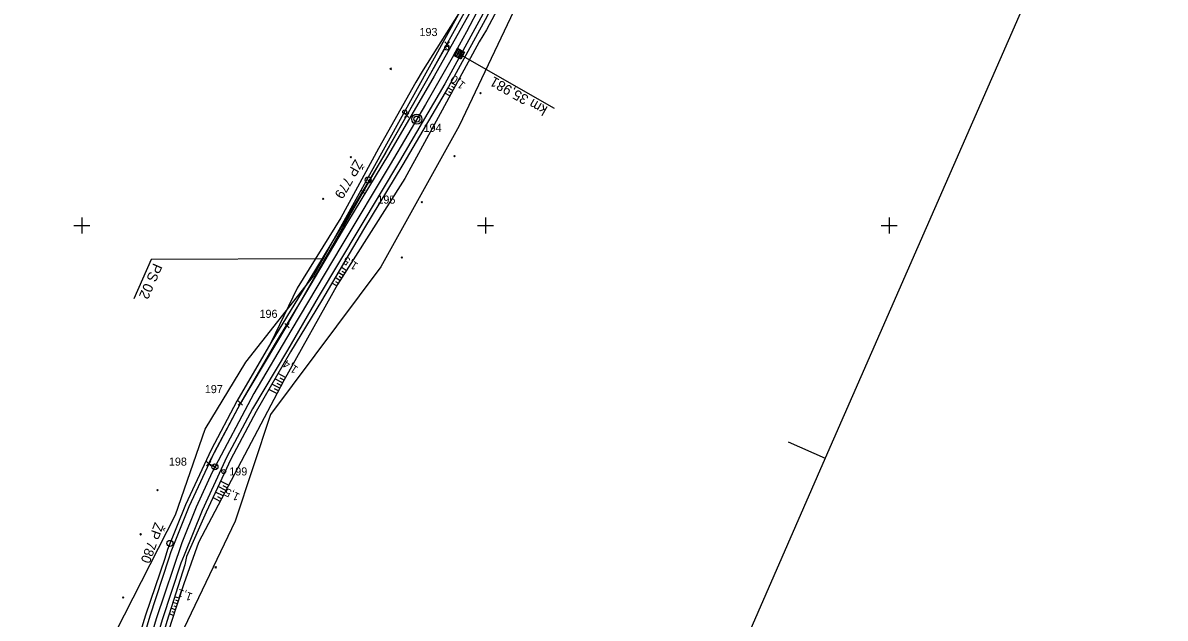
# Model space of a CAD drawing. Extents: x -806856 to -806332, y -1151642 to -1150946.
# Drawn here: x -806614.6 to -806331.6, y -1151297.3 to -1151149.8 of the extents above; entities that cross this region are included whole.
import ezdxf

# ---------------------------------------------------------------- set-up
doc = ezdxf.new("R2010")
doc.units = 0
for name, color, linetype in [('0381KM032-037P - Vrstva 1', 7, 'Continuous'), ('0381KM032-037P - Vrstva 27', 7, 'Continuous'), ('0381KM032-037P - Vrstva 3', 7, 'Continuous'), ('0381KM032-037P - Vrstva 4', 7, 'Continuous'), ('0381KM032-037P - Vrstva 48', 7, 'Continuous'), ('0381KM032-037P - Vrstva 49', 7, 'Continuous'), ('0381KM032-037P - Vrstva 7', 7, 'Continuous'), ('Default', 7, 'Continuous'), ('formát', 7, 'Continuous'), ('hran DP - hran DP', 7, 'Continuous'), ('krizky_1000 - Vrstva 1', 7, 'Continuous'), ('PSR_C2_2_Lomove_body_Vimperk - Vrstva 60', 7, 'Continuous'), ('PSR_C2_2_trasa_Vimperk - Kabelová trasa', 7, 'Continuous'), ('SOPS', 7, 'Continuous'), ('vyt_sit - ohrožené', 7, 'Continuous'), ('vyt_sit - stávající', 7, 'Continuous')]:
    doc.layers.add(name, color=color, linetype=linetype)

msp = doc.modelspace()

# ---------------------------------------------------------------- linework, layer by layer
at = {"layer": '0381KM032-037P - Vrstva 1'}
for points in [[(-806459.11, -1151042.15), (-806463.27, -1151055.58), (-806467.76, -1151068.75), (-806472.65, -1151081.99), (-806477.96, -1151095.43), (-806483.66, -1151108.91), (-806489.46, -1151121.74), (-806491.74, -1151126.53), (-806497.91, -1151139.08), (-806504.69, -1151152.02), (-806507.41, -1151157), (-806508.24, -1151158.47)], [(-806508.24, -1151158.47), (-806514.85, -1151170.04), (-806523.65, -1151184.88)], [(-806523.65, -1151184.88), (-806535.6, -1151204.92), (-806548.25, -1151226.13)], [(-806548.25, -1151226.13), (-806557.37, -1151241.69), (-806567.71, -1151261.13)], [(-806567.71, -1151261.13), (-806571.7, -1151269.85), (-806575.25, -1151278.64)], [(-806575.26, -1151278.66), (-806581.61, -1151297.45), (-806587.32, -1151317.2)]]:
    msp.add_lwpolyline(points, dxfattribs=at)
at = {"layer": '0381KM032-037P - Vrstva 27'}
msp.add_line((-806509.65, -1151156.05), (-806509.55, -1151156.05), dxfattribs=at)
msp.add_circle((-806509.6, -1151156.05), 0.5, dxfattribs=at)
at = {"layer": '0381KM032-037P - Vrstva 3'}
for p, q in [((-806507.53, -1151158.07), (-806507.7, -1151157.51)), ((-806507.07, -1151158.32), (-806507.44, -1151157.05)), ((-806507.41, -1151157), (-806483.02, -1151170.91)), ((-806506.6, -1151158.58), (-806507.19, -1151156.58)), ((-806506.14, -1151158.83), (-806506.93, -1151156.12)), ((-806505.88, -1151158.37), (-806506.47, -1151156.37)), ((-806505.63, -1151157.9), (-806506, -1151156.63)), ((-806505.37, -1151157.44), (-806505.54, -1151156.88))]:
    msp.add_line(p, q, dxfattribs=at)
msp.add_lwpolyline([(-806507.89, -1151157.87), (-806506.93, -1151156.12), (-806505.18, -1151157.08), (-806506.14, -1151158.83)], close=True, dxfattribs=at)
at = {"layer": '0381KM032-037P - Vrstva 4'}
for points in [[(-806449.56, -1151013.68), (-806449.62, -1151013.88), (-806452.81, -1151025.46), (-806457.3, -1151041.13), (-806462.78, -1151058.55), (-806470.34, -1151080.36), (-806477.94, -1151099.38), (-806485.55, -1151116.61), (-806493.04, -1151132.58), (-806500.67, -1151147.66), (-806510.08, -1151164.94), (-806521.27, -1151184.09), (-806531.11, -1151200.55)], [(-806448.21, -1151014.27), (-806448.22, -1151014.33), (-806451.54, -1151025.93), (-806456.14, -1151041.58), (-806461.64, -1151059.21), (-806469.17, -1151081.08), (-806476.72, -1151099.82), (-806484.37, -1151117.46), (-806491.94, -1151132.93), (-806500.08, -1151149.04), (-806509.16, -1151165.69), (-806520.46, -1151184.9), (-806530.22, -1151201.05)], [(-806453.41, -1151012), (-806457.09, -1151024.8), (-806461.35, -1151040.24), (-806466.6, -1151057.45), (-806474.53, -1151080.31), (-806481.65, -1151097.72), (-806488.93, -1151114.87), (-806496.54, -1151130.59), (-806504.49, -1151145.86), (-806513.59, -1151162.34)], [(-806452.41, -1151012.43), (-806452.61, -1151013.14), (-806455.7, -1151025.15), (-806460.24, -1151040.55), (-806465.79, -1151057.73), (-806473.74, -1151080.66), (-806480.83, -1151098.02), (-806488.21, -1151115.16), (-806495.76, -1151130.97), (-806503.39, -1151146.39), (-806512.71, -1151163.05)], [(-806513.59, -1151162.34), (-806524.74, -1151181.99), (-806534.73, -1151198.81)], [(-806512.71, -1151163.05), (-806524.03, -1151182.45), (-806534.14, -1151199.19)], [(-806534.73, -1151198.81), (-806545.37, -1151216.39), (-806553.18, -1151229.13), (-806561.58, -1151243.53), (-806567.96, -1151255.6), (-806574.3, -1151269.24), (-806578.76, -1151280.27), (-806579.4, -1151282.54), (-806584.22, -1151296.56), (-806589.48, -1151313.82), (-806594.95, -1151333.92), (-806600.1, -1151352.67), (-806608.81, -1151384.22), (-806613.08, -1151400.58)], [(-806534.14, -1151199.19), (-806544.55, -1151216.75), (-806552.31, -1151229.7), (-806560.71, -1151244.03), (-806567.24, -1151256.24), (-806573.52, -1151269.73), (-806577.97, -1151280.92), (-806578.5, -1151282.67), (-806583.15, -1151296.86), (-806588.26, -1151314.07), (-806594.08, -1151334.22), (-806599.38, -1151352.89), (-806608.02, -1151384.26), (-806612.6, -1151400.79)], [(-806531.11, -1151200.55), (-806541.48, -1151217.8), (-806549.08, -1151230.92), (-806557.69, -1151245.47), (-806564.05, -1151257.36), (-806570.21, -1151270.63), (-806574.62, -1151281.75), (-806575.45, -1151283.67), (-806580.1, -1151297.77), (-806585.12, -1151314.97), (-806590.56, -1151334.63), (-806595.8, -1151353.37), (-806604.61, -1151384.9), (-806609.41, -1151402.19)], [(-806530.22, -1151201.05), (-806540.66, -1151218.65), (-806548.31, -1151231.35), (-806556.78, -1151246.08), (-806563.07, -1151257.89), (-806569.22, -1151271.02), (-806574.1, -1151282.08), (-806574.48, -1151284.1), (-806578.97, -1151298.16), (-806583.83, -1151315.38), (-806589.34, -1151334.88), (-806594.45, -1151353.63), (-806603.42, -1151385.04), (-806608.69, -1151402.5)]]:
    msp.add_lwpolyline(points, dxfattribs=at)
at = {"layer": '0381KM032-037P - Vrstva 48'}
for p, q in [((-806508.1, -1151166.54), (-806509.29, -1151165.9)), ((-806508.45, -1151167.2), (-806509.06, -1151166.88)), ((-806507.39, -1151165.22), (-806508.56, -1151164.59)), ((-806507.74, -1151165.88), (-806508.33, -1151165.56)), ((-806508.81, -1151167.86), (-806510.05, -1151167.2)), ((-806535.27, -1151212.43), (-806536.5, -1151211.65)), ((-806534.47, -1151211.16), (-806535.73, -1151210.35)), ((-806534.87, -1151211.79), (-806535.49, -1151211.4)), ((-806536.85, -1151214.97), (-806538.08, -1151214.31)), ((-806536.08, -1151213.69), (-806537.27, -1151212.94)), ((-806536.48, -1151214.33), (-806537.06, -1151213.95)), ((-806535.67, -1151213.06), (-806536.28, -1151212.68)), ((-806549.55, -1151237.71), (-806551.38, -1151236.68)), ((-806549.91, -1151238.36), (-806550.83, -1151237.85)), ((-806551.66, -1151241.68), (-806553.65, -1151240.63)), ((-806550.96, -1151240.35), (-806552.9, -1151239.33)), ((-806551.31, -1151241.01), (-806552.29, -1151240.5)), ((-806550.26, -1151239.02), (-806552.15, -1151238.03)), ((-806550.61, -1151239.69), (-806551.57, -1151239.18)), ((-806563.63, -1151264.4), (-806565.62, -1151263.35)), ((-806565.02, -1151267.05), (-806566.9, -1151266.07)), ((-806564.33, -1151265.73), (-806566.26, -1151264.71)), ((-806564.67, -1151266.39), (-806565.63, -1151265.89)), ((-806563.97, -1151265.06), (-806564.96, -1151264.54)), ((-806565.72, -1151268.38), (-806567.54, -1151267.43)), ((-806565.37, -1151267.72), (-806566.3, -1151267.23)), ((-806576.33, -1151293.8), (-806577.46, -1151293.43)), ((-806576.56, -1151294.51), (-806577.15, -1151294.32)), ((-806575.86, -1151292.37), (-806577, -1151292)), ((-806576.1, -1151293.08), (-806576.71, -1151292.89)), ((-806577.26, -1151296.65), (-806578.37, -1151296.29)), ((-806576.79, -1151295.22), (-806577.92, -1151294.86)), ((-806577.02, -1151295.94), (-806577.6, -1151295.75))]:
    msp.add_line(p, q, dxfattribs=at)
at = {"layer": '0381KM032-037P - Vrstva 49'}
for p, q in [((-806523.3, -1151161.03), (-806523.66, -1151161.38)), ((-806523.66, -1151161.03), (-806523.3, -1151161.38)), ((-806501.03, -1151167.07), (-806501.39, -1151167.43)), ((-806501.39, -1151167.08), (-806501.03, -1151167.43)), ((-806533.51, -1151182.94), (-806533.15, -1151183.29)), ((-806533.15, -1151182.94), (-806533.5, -1151183.29)), ((-806507.48, -1151182.67), (-806507.84, -1151183.02)), ((-806507.84, -1151182.67), (-806507.48, -1151183.02)), ((-806540.04, -1151193.21), (-806540.39, -1151193.57)), ((-806540.39, -1151193.21), (-806540.03, -1151193.57)), ((-806515.61, -1151194.06), (-806515.96, -1151194.41)), ((-806515.96, -1151194.06), (-806515.61, -1151194.41)), ((-806520.55, -1151207.75), (-806520.9, -1151208.11)), ((-806520.9, -1151207.76), (-806520.54, -1151208.11)), ((-806581.43, -1151265.45), (-806581.07, -1151265.8)), ((-806581.07, -1151265.45), (-806581.42, -1151265.81)), ((-806585.29, -1151276.36), (-806585.64, -1151276.72)), ((-806585.64, -1151276.36), (-806585.29, -1151276.72)), ((-806566.67, -1151284.56), (-806567.02, -1151284.92)), ((-806567.02, -1151284.56), (-806566.66, -1151284.92)), ((-806589.55, -1151292.05), (-806589.91, -1151292.41)), ((-806589.91, -1151292.05), (-806589.55, -1151292.41))]:
    msp.add_line(p, q, dxfattribs=at)
for points in [[(-806448.2, -1151014.28), (-806448.22, -1151014.33), (-806451.54, -1151025.93), (-806456.14, -1151041.58), (-806461.64, -1151059.21), (-806469.17, -1151081.08), (-806476.72, -1151099.82), (-806484.37, -1151117.46), (-806491.94, -1151132.93), (-806500.08, -1151149.04), (-806509.16, -1151165.69), (-806520.46, -1151184.9), (-806530.22, -1151201.05)], [(-806446.83, -1151014.88), (-806447.16, -1151016), (-806450, -1151026.43), (-806453.97, -1151042.26), (-806459.11, -1151060.35), (-806468.36, -1151084.26), (-806475.1, -1151100.8), (-806483.46, -1151117.96), (-806490.37, -1151133.75), (-806499.76, -1151151.57), (-806501.59, -1151154.48), (-806510.73, -1151171.42), (-806520.01, -1151188.39)], [(-806496.54, -1151130.59), (-806505.32, -1151145.34), (-806515.42, -1151161.45), (-806517.29, -1151164.53), (-806526.47, -1151180.94), (-806535.85, -1151198.12)], [(-806520.01, -1151188.39), (-806536.66, -1151214.61), (-806549.93, -1151238.4), (-806571.09, -1151278.57), (-806574.7, -1151288.79), (-806577.92, -1151298.67), (-806582.99, -1151315.77), (-806588.39, -1151335.12), (-806593.7, -1151353.88), (-806600.16, -1151386.57)], [(-806535.85, -1151198.12), (-806546.61, -1151215.57), (-806553.18, -1151229.13), (-806561.58, -1151243.53), (-806567.96, -1151255.6), (-806574.3, -1151269.24), (-806578.76, -1151280.27), (-806579.4, -1151282.54), (-806584.22, -1151296.56), (-806589.48, -1151313.82), (-806594.95, -1151333.92), (-806600.1, -1151352.67), (-806608.81, -1151384.22), (-806614.6, -1151399.91)], [(-806530.22, -1151201.05), (-806540.66, -1151218.65), (-806548.31, -1151231.35), (-806556.78, -1151246.08), (-806563.07, -1151257.89), (-806569.22, -1151271.02), (-806574.1, -1151282.08)], [(-806574.1, -1151282.08), (-806574.48, -1151284.1), (-806578.97, -1151298.16), (-806583.83, -1151315.38), (-806589.34, -1151334.88), (-806594.45, -1151353.63), (-806603.42, -1151385.04), (-806608.48, -1151402.59)]]:
    msp.add_lwpolyline(points, dxfattribs=at)
at = {"layer": '0381KM032-037P - Vrstva 7'}
for p, q in [((-806520.04, -1151171.89), (-806519.94, -1151171.89)), ((-806564.89, -1151260.99), (-806564.79, -1151260.99))]:
    msp.add_line(p, q, dxfattribs=at)
for centre, radius in [((-806519.99, -1151171.89), 0.5), ((-806517, -1151173.66), 1.25), ((-806517, -1151173.66), 0.752), ((-806567.02, -1151259.83), 0.75), ((-806564.84, -1151260.99), 0.5)]:
    msp.add_circle(centre, radius, dxfattribs=at)
at = {"layer": 'formát'}
for p, q in [((-806331.63, -1151065.3), (-806415.83, -1151257.68)), ((-806424.99, -1151253.67), (-806415.83, -1151257.68)), ((-806424.99, -1151253.67), (-806415.83, -1151257.68)), ((-806415.83, -1151257.68), (-806500.03, -1151450.06))]:
    msp.add_line(p, q, dxfattribs=at)
at = {"layer": 'hran DP - hran DP'}
for p, q in [((-806485.36, -1151130.76), (-806506.53, -1151175.36)), ((-806542.64, -1151212.58), (-806506.25, -1151146.99)), ((-806506.53, -1151175.36), (-806525.91, -1151210.3)), ((-806525.91, -1151210.3), (-806553.28, -1151246.87)), ((-806559.38, -1151233.91), (-806542.64, -1151212.58)), ((-806569.42, -1151250.48), (-806559.38, -1151233.91)), ((-806553.28, -1151246.87), (-806561.98, -1151273.31)), ((-806576.79, -1151271.69), (-806569.42, -1151250.48)), ((-806591.51, -1151300.57), (-806576.79, -1151271.69)), ((-806561.98, -1151273.31), (-806579.39, -1151309.52))]:
    msp.add_line(p, q, dxfattribs=at)
at = {"layer": 'krizky_1000 - Vrstva 1'}
for points in [[(-806600, -1151198), (-806600, -1151202)], [(-806500, -1151198), (-806500, -1151202)], [(-806400, -1151198), (-806400, -1151202)], [(-806602, -1151200), (-806598, -1151200)], [(-806502, -1151200), (-806498, -1151200)], [(-806402, -1151200), (-806398, -1151200)]]:
    msp.add_lwpolyline(points, dxfattribs=at)
at = {"layer": 'PSR_C2_2_Lomove_body_Vimperk - Vrstva 60'}
for p, q in [((-806510.05, -1151155.64), (-806508.95, -1151154.54)), ((-806508.95, -1151155.64), (-806510.05, -1151154.54)), ((-806520.07, -1151173.25), (-806518.97, -1151172.15)), ((-806518.97, -1151173.25), (-806520.07, -1151172.15)), ((-806530.89, -1151192.26), (-806529.79, -1151191.16)), ((-806529.79, -1151192.26), (-806530.89, -1151191.16)), ((-806549.73, -1151225.37), (-806548.63, -1151224.27)), ((-806548.63, -1151225.37), (-806549.73, -1151224.27)), ((-806561.26, -1151244.58), (-806560.16, -1151243.48)), ((-806560.16, -1151244.58), (-806561.26, -1151243.48)), ((-806569.13, -1151259.57), (-806568.03, -1151258.47)), ((-806568.03, -1151259.57), (-806569.13, -1151258.47)), ((-806567.58, -1151260.39), (-806566.48, -1151259.29)), ((-806566.48, -1151260.39), (-806567.58, -1151259.29))]:
    msp.add_line(p, q, dxfattribs=at)
at = {"layer": 'PSR_C2_2_trasa_Vimperk - Kabelová trasa'}
msp.add_lwpolyline([(-806509.5, -1151155.09), (-806519.52, -1151172.7), (-806530.34, -1151191.71), (-806549.18, -1151224.82), (-806560.71, -1151244.03), (-806568.58, -1151259.02), (-806567.03, -1151259.84)], dxfattribs=at)
at = {"layer": 'SOPS'}
msp.add_lwpolyline([(-806539.76, -1151208.26), (-806582.82, -1151208.45), (-806587.09, -1151218.2)], dxfattribs=at)
at = {"layer": 'vyt_sit - ohrožené'}
msp.add_line((-806529.11, -1151188.76), (-806529.01, -1151188.76), dxfattribs=at)
msp.add_circle((-806529.06, -1151188.76), 0.756, dxfattribs=at)
at = {"layer": 'vyt_sit - stávající'}
msp.add_line((-806578.22, -1151278.81), (-806578.12, -1151278.81), dxfattribs=at)
msp.add_circle((-806578.18, -1151278.81), 0.756, dxfattribs=at)

# ---------------------------------------------------------------- texts
at = {"layer": '0381KM032-037P - Vrstva 3'}
msp.add_text('km 35,981', height=2.5, rotation=150.2693, dxfattribs=at).set_placement((-806484.41, -1151170.73))
at = {"layer": '0381KM032-037P - Vrstva 48'}
for s, rotation, p in [('1,0', 142.0922, (-806504.79, -1151164.89)), ('1,5', 147.9162, (-806531.38, -1151209.56)), ('1,4', 147.0433, (-806546.24, -1151235.23)), ('1,5', 154.8905, (-806560.68, -1151266.6)), ('1,1', 160.7839, (-806572.42, -1151291.27))]:
    msp.add_text(s, height=2, rotation=rotation, dxfattribs=at).set_placement(p)
at = {"layer": 'Default'}
for s, p in [('193', (-806516.35, -1151153.08)), ('194', (-806515.34, -1151176.82)), ('195', (-806526.78, -1151194.61)), ('196', (-806555.98, -1151222.91)), ('197', (-806569.53, -1151241.56)), ('198', (-806578.43, -1151259.53)), ('199', (-806563.47, -1151261.96))]:
    msp.add_text(s, height=2, dxfattribs=at).set_placement(p)
at = {"layer": 'SOPS'}
msp.add_text('PS 02', height=2.5, rotation=246.3629, dxfattribs=at).set_placement((-806582.26, -1151209.18))
at = {"layer": 'vyt_sit - ohrožené'}
msp.add_text('ŽP 779', height=2.4, rotation=240, dxfattribs=at).set_placement((-806532.3, -1151183.48))
at = {"layer": 'vyt_sit - stávající'}
msp.add_text('ŽP 780', height=2.4, rotation=250, dxfattribs=at).set_placement((-806581.91, -1151273.42))

doc.saveas('drawing.dxf')
